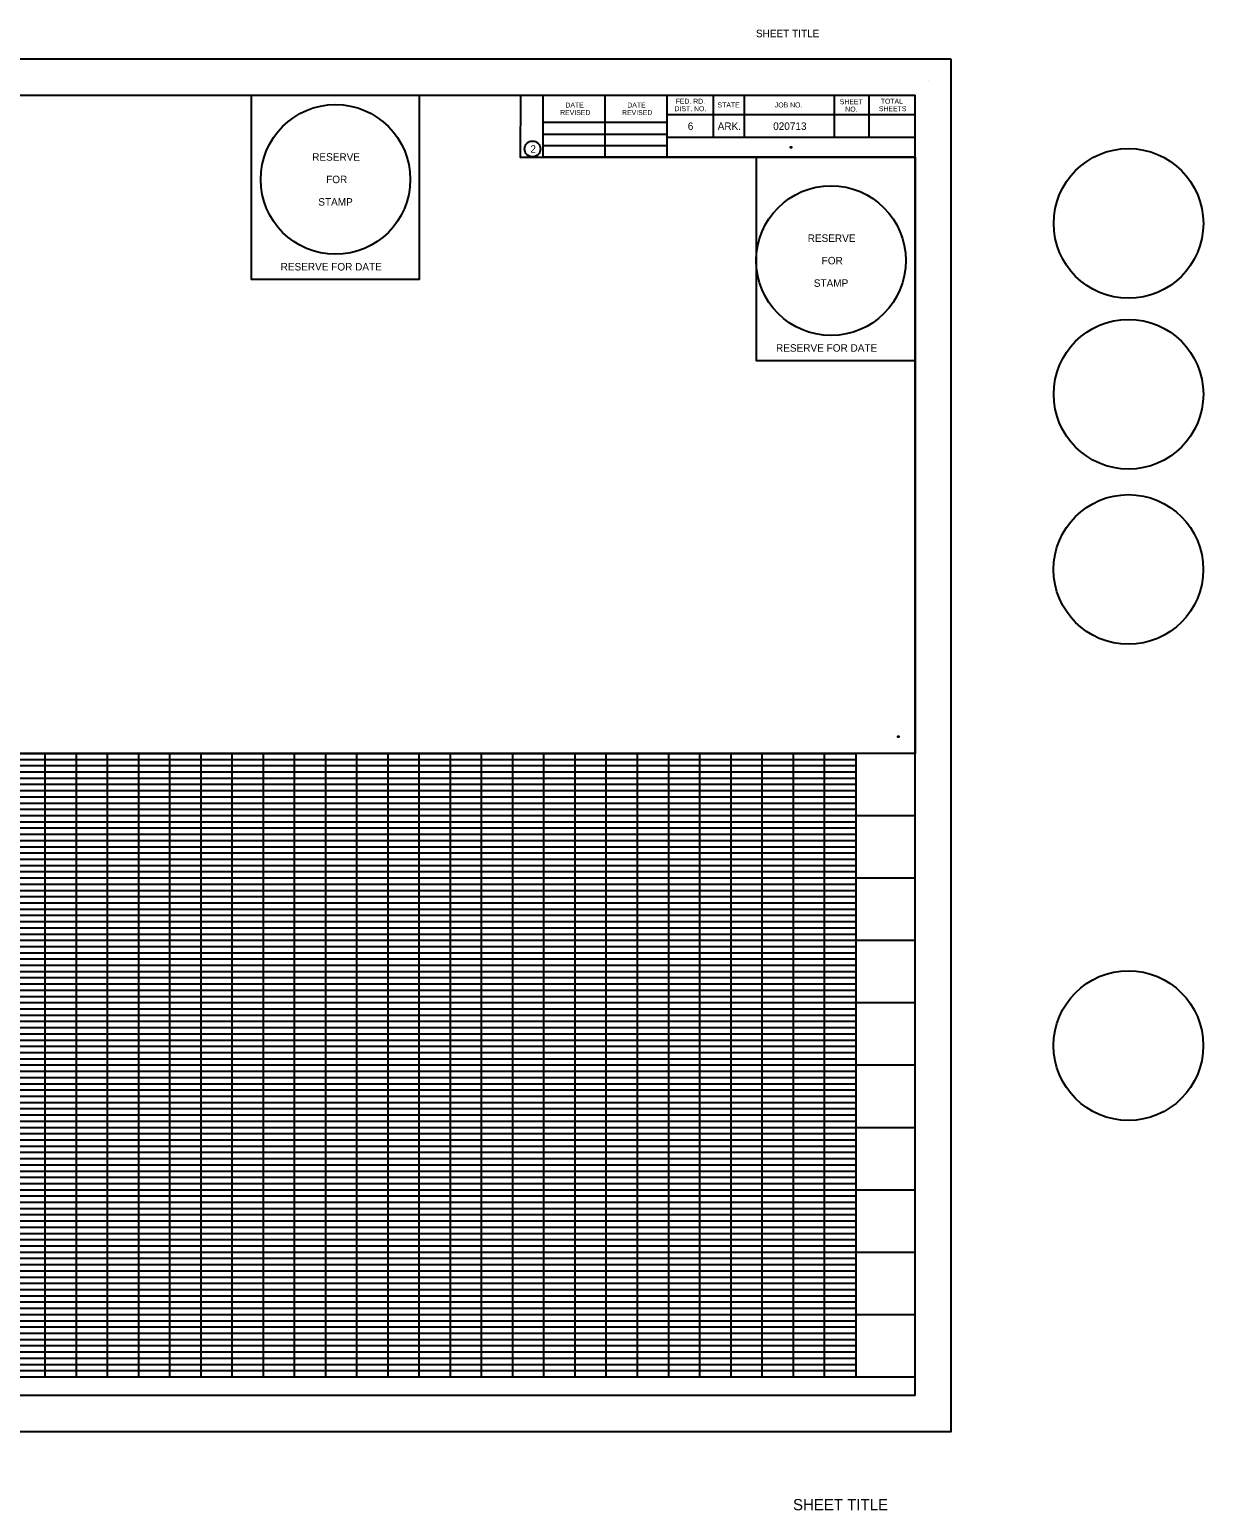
# Model space of a CAD drawing. Extents: x 0 to 19, y -0.6 to 11.2.
# Drawn here: x 9.61 to 19.02, y -0.63 to 11.24 of the extents above; entities that cross this region are included whole.
import ezdxf

# ---------------------------------------------------------------- set-up
doc = ezdxf.new("R2010")
doc.units = 0
for name, color, linetype in [('G-ANNO-TEXT', 7, 'Continuous'), ('G-Border-Paper', 7, 'Continuous'), ('G-Border-Sheet', 7, 'Continuous'), ('G-Grid-Border', 7, 'Continuous'), ('G-Grid-Major', 7, 'Continuous'), ('G-Grid-Minor', 7, 'Continuous'), ('G-No Plot-Anchor', 7, 'Continuous'), ('G-No Plot-Border-1', 7, 'Continuous'), ('G-No Plot-Border-2', 7, 'Continuous'), ('G-No Plot-Stamp-1', 7, 'Continuous'), ('G-No Plot-Stamp-2', 7, 'Continuous'), ('G-Table-Major', 7, 'Continuous'), ('G-Table-Minor', 7, 'Continuous')]:
    doc.layers.add(name, color=color, linetype=linetype)

msp = doc.modelspace()

# ---------------------------------------------------------------- linework, layer by layer
at = {"layer": 'G-ANNO-TEXT'}
msp.add_line((16.821, 10.827), (16.821, 10.827), dxfattribs=at)
at = {"layer": 'G-Border-Paper'}
msp.add_lwpolyline([(17, 11), (0, 11), (0, 0), (17, 0)], close=True, dxfattribs=at)
at = {"layer": 'G-Border-Sheet'}
for p, q in [((0.758, 10.712), (16.712, 10.712)), ((16.712, 0.288), (16.712, 10.712)), ((16.712, 0.288), (0.758, 0.288))]:
    msp.add_line(p, q, dxfattribs=at)
at = {"layer": 'G-Grid-Border'}
for p, q in [((16.712, 5.435), (0.758, 5.435)), ((16.712, 0.435), (0.758, 0.435))]:
    msp.add_line(p, q, dxfattribs=at)
msp.add_lwpolyline([(1.235, 5.435), (16.235, 5.435), (16.235, 0.435), (1.235, 0.435)], close=True, dxfattribs=at)
at = {"layer": 'G-Grid-Major'}
for p, q in [((9.735, 0.435), (9.735, 5.435)), ((10.235, 0.435), (10.235, 5.435)), ((10.735, 0.435), (10.735, 5.435)), ((11.235, 0.435), (11.235, 5.435)), ((11.735, 0.435), (11.735, 5.435)), ((12.235, 0.435), (12.235, 5.435)), ((12.735, 0.435), (12.735, 5.435)), ((13.235, 0.435), (13.235, 5.435)), ((13.735, 0.435), (13.735, 5.435)), ((14.235, 0.435), (14.235, 5.435)), ((14.735, 0.435), (14.735, 5.435)), ((15.235, 0.435), (15.235, 5.435)), ((15.735, 0.435), (15.735, 5.435)), ((16.712, 4.935), (0.758, 4.935)), ((16.712, 4.435), (0.758, 4.435)), ((16.712, 3.935), (0.758, 3.935)), ((16.712, 3.435), (0.758, 3.435)), ((16.712, 2.935), (0.758, 2.935)), ((16.712, 2.435), (0.758, 2.435)), ((16.712, 1.935), (0.758, 1.935)), ((16.712, 1.435), (0.758, 1.435)), ((16.712, 0.935), (0.758, 0.935))]:
    msp.add_line(p, q, dxfattribs=at)
msp.add_lwpolyline([(1.235, 5.435), (16.235, 5.435), (16.235, 0.435), (1.235, 0.435)], close=True, dxfattribs=at)
at = {"layer": 'G-Grid-Minor'}
for p, q in [((16.235, 5.385), (1.235, 5.385)), ((9.985, 0.435), (9.985, 5.435)), ((10.485, 0.435), (10.485, 5.435)), ((10.985, 0.435), (10.985, 5.435)), ((11.485, 0.435), (11.485, 5.435)), ((11.985, 0.435), (11.985, 5.435)), ((12.485, 0.435), (12.485, 5.435)), ((12.985, 0.435), (12.985, 5.435)), ((13.485, 0.435), (13.485, 5.435)), ((13.985, 0.435), (13.985, 5.435)), ((14.485, 0.435), (14.485, 5.435)), ((14.985, 0.435), (14.985, 5.435)), ((15.485, 0.435), (15.485, 5.435)), ((15.985, 0.435), (15.985, 5.435)), ((16.235, 5.335), (1.235, 5.335)), ((16.235, 5.285), (1.235, 5.285)), ((16.235, 5.235), (1.235, 5.235)), ((16.235, 5.185), (1.235, 5.185)), ((16.235, 5.135), (1.235, 5.135)), ((16.235, 5.085), (1.235, 5.085)), ((16.235, 5.035), (1.235, 5.035)), ((16.235, 4.985), (1.235, 4.985)), ((16.235, 4.885), (1.235, 4.885)), ((16.235, 4.835), (1.235, 4.835)), ((16.235, 4.785), (1.235, 4.785)), ((16.235, 4.735), (1.235, 4.735)), ((16.235, 4.685), (1.235, 4.685)), ((16.235, 4.635), (1.235, 4.635)), ((16.235, 4.585), (1.235, 4.585)), ((16.235, 4.535), (1.235, 4.535)), ((16.235, 4.485), (1.235, 4.485)), ((16.235, 4.385), (1.235, 4.385)), ((16.235, 4.335), (1.235, 4.335)), ((16.235, 4.285), (1.235, 4.285)), ((16.235, 4.235), (1.235, 4.235)), ((16.235, 4.185), (1.235, 4.185)), ((16.235, 4.135), (1.235, 4.135)), ((16.235, 4.085), (1.235, 4.085)), ((16.235, 4.035), (1.235, 4.035)), ((16.235, 3.985), (1.235, 3.985)), ((16.235, 3.885), (1.235, 3.885)), ((16.235, 3.835), (1.235, 3.835)), ((16.235, 3.785), (1.235, 3.785)), ((16.235, 3.735), (1.235, 3.735)), ((16.235, 3.685), (1.235, 3.685)), ((16.235, 3.635), (1.235, 3.635)), ((16.235, 3.585), (1.235, 3.585)), ((16.235, 3.535), (1.235, 3.535)), ((16.235, 3.485), (1.235, 3.485)), ((16.235, 3.385), (1.235, 3.385)), ((16.235, 3.335), (1.235, 3.335)), ((16.235, 3.285), (1.235, 3.285)), ((16.235, 3.235), (1.235, 3.235)), ((16.235, 3.185), (1.235, 3.185)), ((16.235, 3.135), (1.235, 3.135)), ((16.235, 3.085), (1.235, 3.085)), ((16.235, 3.035), (1.235, 3.035)), ((16.235, 2.985), (1.235, 2.985)), ((16.235, 2.885), (1.235, 2.885)), ((16.235, 2.835), (1.235, 2.835)), ((16.235, 2.785), (1.235, 2.785)), ((16.235, 2.735), (1.235, 2.735)), ((16.235, 2.685), (1.235, 2.685)), ((16.235, 2.635), (1.235, 2.635)), ((16.235, 2.585), (1.235, 2.585)), ((16.235, 2.535), (1.235, 2.535)), ((16.235, 2.485), (1.235, 2.485)), ((16.235, 2.385), (1.235, 2.385)), ((16.235, 2.335), (1.235, 2.335)), ((16.235, 2.285), (1.235, 2.285)), ((16.235, 2.235), (1.235, 2.235)), ((16.235, 2.185), (1.235, 2.185)), ((16.235, 2.135), (1.235, 2.135)), ((16.235, 2.085), (1.235, 2.085)), ((16.235, 2.035), (1.235, 2.035)), ((16.235, 1.985), (1.235, 1.985)), ((16.235, 1.885), (1.235, 1.885)), ((16.235, 1.835), (1.235, 1.835)), ((16.235, 1.785), (1.235, 1.785)), ((16.235, 1.735), (1.235, 1.735)), ((16.235, 1.685), (1.235, 1.685)), ((16.235, 1.635), (1.235, 1.635)), ((16.235, 1.585), (1.235, 1.585)), ((16.235, 1.535), (1.235, 1.535)), ((16.235, 1.485), (1.235, 1.485)), ((16.235, 1.385), (1.235, 1.385)), ((16.235, 1.335), (1.235, 1.335)), ((16.235, 1.285), (1.235, 1.285)), ((16.235, 1.235), (1.235, 1.235)), ((16.235, 1.185), (1.235, 1.185)), ((16.235, 1.135), (1.235, 1.135)), ((16.235, 1.085), (1.235, 1.085)), ((16.235, 1.035), (1.235, 1.035)), ((16.235, 0.985), (1.235, 0.985)), ((16.235, 0.885), (1.235, 0.885)), ((16.235, 0.835), (1.235, 0.835)), ((16.235, 0.785), (1.235, 0.785)), ((16.235, 0.735), (1.235, 0.735)), ((16.235, 0.685), (1.235, 0.685)), ((16.235, 0.635), (1.235, 0.635)), ((16.235, 0.585), (1.235, 0.585)), ((16.235, 0.535), (1.235, 0.535)), ((16.235, 0.485), (1.235, 0.485))]:
    msp.add_line(p, q, dxfattribs=at)
at = {"layer": 'G-No Plot-Anchor'}
for centre in [(15.716, 10.294), (16.577, 5.57)]:
    msp.add_circle(centre, 0.005, dxfattribs=at)
at = {"layer": 'G-No Plot-Border-1'}
msp.add_lwpolyline([(0.758, 5.435), (0.758, 10.712), (12.738, 10.712), (13.548, 10.712), (13.545, 10.216), (14.721, 10.216), (14.721, 10.216), (15.437, 10.216), (15.437, 8.586), (16.712, 8.586), (16.712, 5.435)], close=True, dxfattribs=at)
at = {"layer": 'G-No Plot-Border-2'}
msp.add_lwpolyline([(0.758, 5.435), (0.758, 10.712), (11.388, 10.712), (11.388, 9.237), (12.738, 9.237), (12.738, 10.712), (13.548, 10.712), (13.545, 10.216), (16.712, 10.216), (16.712, 5.435)], close=True, dxfattribs=at)
at = {"layer": 'G-No Plot-Stamp-1'}
msp.add_circle((16.037, 9.386), 0.6, dxfattribs=at)
at = {"layer": 'G-No Plot-Stamp-2'}
for centre in [(12.063, 10.037), (18.423, 9.684), (18.423, 8.315), (18.422, 6.91), (18.422, 3.093)]:
    msp.add_circle(centre, 0.6, dxfattribs=at)
at = {"layer": 'G-Table-Major'}
for p, q in [((13.728, 10.217), (13.728, 10.712)), ((14.721, 10.712), (14.721, 10.216)), ((13.728, 10.495), (14.721, 10.495)), ((16.712, 10.216), (13.728, 10.216))]:
    msp.add_line(p, q, dxfattribs=at)
msp.add_circle((13.643, 10.281), 0.0638, dxfattribs=at)
at = {"layer": 'G-Table-Minor'}
for p, q in [((14.226, 10.216), (14.226, 10.712)), ((15.093, 10.712), (15.093, 10.372)), ((15.341, 10.712), (15.341, 10.372)), ((16.062, 10.712), (16.062, 10.372)), ((16.34, 10.712), (16.34, 10.372)), ((16.712, 10.566), (16.712, 10.566)), ((16.712, 10.556), (14.721, 10.556)), ((13.728, 10.401), (14.721, 10.401)), ((16.712, 10.372), (14.721, 10.372)), ((13.728, 10.31), (14.721, 10.31))]:
    msp.add_line(p, q, dxfattribs=at)

# ---------------------------------------------------------------- texts
at = {"layer": 'G-ANNO-TEXT'}
for s, height, p in [('SHEET TITLE', 0.06, (15.435, 11.177)), ('TOTAL', 0.04, (16.436, 10.644)), ('REVISED', 0.04, (13.865, 10.553)), ('DATE', 0.04, (13.907, 10.613)), ('REVISED', 0.04, (14.361, 10.553)), ('DATE', 0.04, (14.403, 10.613)), ('DIST. NO.', 0.04, (14.782, 10.584)), ('FED. RD.', 0.04, (14.791, 10.644)), ('STATE', 0.04, (15.127, 10.614)), ('JOB NO.', 0.04, (15.586, 10.614)), ('SHEET', 0.04, (16.107, 10.64)), ('NO.', 0.04, (16.151, 10.58)), ('SHEETS', 0.04, (16.421, 10.584)), ('6', 0.06, (14.888, 10.434)), ('ARK.', 0.06, (15.128, 10.434)), ('020713', 0.06, (15.573, 10.434)), ('2', 0.06, (13.626, 10.251)), ('SHEET TITLE', 0.09, (15.732, -0.632))]:
    msp.add_text(s, height=height, dxfattribs=at).set_placement(p)
at = {"layer": 'G-No Plot-Stamp-1'}
for s, p in [('RESERVE', (15.85, 9.536)), ('FOR ', (15.962, 9.356)), ('STAMP', (15.899, 9.176)), ('RESERVE FOR DATE', (15.596, 8.656))]:
    msp.add_text(s, height=0.06, dxfattribs=at).set_placement(p)
at = {"layer": 'G-No Plot-Stamp-2'}
for s, p in [('RESERVE', (11.876, 10.187)), ('FOR ', (11.988, 10.007)), ('STAMP', (11.925, 9.827)), ('RESERVE FOR DATE', (11.623, 9.307))]:
    msp.add_text(s, height=0.06, dxfattribs=at).set_placement(p)

doc.saveas('drawing.dxf')
